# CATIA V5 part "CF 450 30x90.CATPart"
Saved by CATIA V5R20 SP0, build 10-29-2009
Part number: CF 450 30x90
Definition: NONE
Nomenclature: CF 450 30x90
Source: Unknown
Description: CF 450 30x90
Bounding box of the stored display mesh (mm): x -26.5 to 26.5, y 0 to 90, z -26.5 to 26.5
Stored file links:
  C:\Users\Utente\Desktop\IO LAVORO\3D X SITO CF\X SITO\CF 450\CF 450 30x90.CATPart
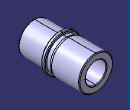
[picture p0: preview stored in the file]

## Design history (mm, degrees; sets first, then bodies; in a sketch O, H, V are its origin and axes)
Body1 "CF 450 30x90" (main body)
  Solid1: solid without history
